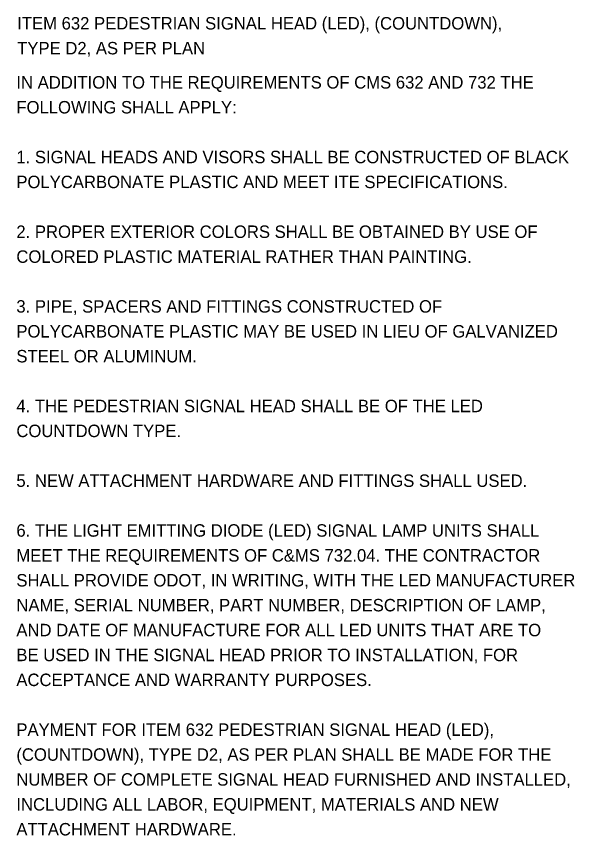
# Model space of a CAD drawing. Extents: x -18.7 to 62.3, y -3.1 to 33.6.
# Drawn here: x 39.48 to 45.75, y -3.14 to 6.08 of the extents above; entities that cross this region are included whole.
import ezdxf

# ---------------------------------------------------------------- set-up
doc = ezdxf.new("R2010")
doc.units = 0
doc.layers.add('SH_Text', color=7, linetype='Continuous')

msp = doc.modelspace()

# ---------------------------------------------------------------- texts
at = {"layer": 'SH_Text'}
for s, p in [('ITEM 632 PEDESTRIAN SIGNAL HEAD (LED), (COUNTDOWN), ', (39.4885, 5.9297)), ('TYPE D2, AS PER PLAN', (39.4885, 5.6497)), ('IN ADDITION TO THE REQUIREMENTS OF CMS 632 AND 732 THE ', (39.4793, 5.2654)), ('FOLLOWING SHALL APPLY:', (39.4793, 4.9854)), ('1. SIGNAL HEADS AND VISORS SHALL BE CONSTRUCTED OF BLACK ', (39.4793, 4.4254)), ('POLYCARBONATE PLASTIC AND MEET ITE SPECIFICATIONS.', (39.4793, 4.1454)), ('2. PROPER EXTERIOR COLORS SHALL BE OBTAINED BY USE OF ', (39.4793, 3.5854)), ('COLORED PLASTIC MATERIAL RATHER THAN PAINTING.', (39.4793, 3.3054)), ('3. PIPE, SPACERS AND FITTINGS CONSTRUCTED OF ', (39.4793, 2.7454)), ('POLYCARBONATE PLASTIC MAY BE USED IN LIEU OF GALVANIZED ', (39.4793, 2.4654)), ('STEEL OR ALUMINUM.', (39.4793, 2.1854)), ('4. THE PEDESTRIAN SIGNAL HEAD SHALL BE OF THE LED ', (39.4793, 1.6254)), ('COUNTDOWN TYPE.', (39.4793, 1.3454)), ('5. NEW ATTACHMENT HARDWARE AND FITTINGS SHALL USED.', (39.4793, 0.7854)), ('6. THE LIGHT EMITTING DIODE (LED) SIGNAL LAMP UNITS SHALL ', (39.4793, 0.2254)), ('MEET THE REQUIREMENTS OF C&MS 732.04. THE CONTRACTOR ', (39.4793, -0.0546)), ('SHALL PROVIDE ODOT, IN WRITING, WITH THE LED MANUFACTURER ', (39.4793, -0.3346)), ('NAME, SERIAL NUMBER, PART NUMBER, DESCRIPTION OF LAMP, ', (39.4793, -0.6146)), ('AND DATE OF MANUFACTURE FOR ALL LED UNITS THAT ARE TO ', (39.4793, -0.8946)), ('BE USED IN THE SIGNAL HEAD PRIOR TO INSTALLATION, FOR ', (39.4793, -1.1746)), ('ACCEPTANCE AND WARRANTY PURPOSES.', (39.4793, -1.4546)), ('PAYMENT FOR ITEM 632 PEDESTRIAN SIGNAL HEAD (LED), ', (39.4793, -2.0146)), ('(COUNTDOWN), TYPE D2, AS PER PLAN SHALL BE MADE FOR THE ', (39.4793, -2.2946)), ('NUMBER OF COMPLETE SIGNAL HEAD FURNISHED AND INSTALLED, ', (39.4793, -2.5746)), ('INCLUDING ALL LABOR, EQUIPMENT, MATERIALS AND NEW ', (39.4793, -2.8546)), ('ATTACHMENT HARDWARE.', (39.4793, -3.1346))]:
    msp.add_text(s, height=0.14, dxfattribs=at).set_placement(p)

doc.saveas('drawing.dxf')
